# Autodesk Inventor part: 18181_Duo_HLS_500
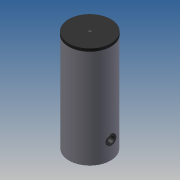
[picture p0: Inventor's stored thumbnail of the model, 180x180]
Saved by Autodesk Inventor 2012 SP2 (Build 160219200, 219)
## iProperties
allow_slope_adjustment: 0 ul
connection_type: 13 ul
flow_configuration2: 1 ul
flow_direction: 2 ul
loss_method: 0 ul
radius: 12,250 mm
radius: 19,625 mm
radius: 15,375 mm
description: 0:0:18181_Duo_HLS_500
manufacturer: 0:0:Flamco Group
model: 0:0:Duo HLS 500
url: 0:0:www.flamcogroup.com
Created: 2014-05
Part Number: 18181_Duo_HLS_500
Material: Default
Document SubType Name: Modeling
Designer: michel
Density: 1 g/cm^3
Author: michel
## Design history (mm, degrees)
sketch "Sketch1"
  geometry: C1 r 375 at (0, 0); 1 further point
  constraints: 1 centre point, 1 coincident
  dimensions: "d0" = 750 diameter of C1
extrude "Extrusion1" new body sketch "Sketch1" distance "d1" = 1830; taper "d2" = 0 deg
sketch "Sketch2"
  geometry: L1 (-375, 1830)-(375, 1830) reference; L2 (-375, 0)-(375, 0) reference; L3 (-375, 0)-(-375, 1830) reference; L4 (0, -326)-(0, 1956) reference; L5 (-504, 70)-(536, 70); L6 (-504, 330)-(536, 330); L7 (-490, 990)-(536, 990); L8 (-490, 1090)-(536, 1090); L9 (-490, 1670)-(536, 1670); L10 (375, 70)-(335, 70); L11 (335, 70)-(335, 86.625); L12 (335, 86.625)-(375, 86.625); L13 (375, 86.625)-(375, 70); L14 (335, 53.375)-(376, 53.375); L15 (376, 53.375)-(376, 54.625); L16 (376, 54.625)-(335, 54.625); L17 (335, 54.625)-(335, 53.375); L18 (375, 330)-(335, 330); L19 (335, 330)-(335, 350.955); L20 (335, 350.955)-(375, 350.955); L21 (375, 350.955)-(375, 330); L22 (335, 309.045)-(376, 309.045); L23 (376, 309.045)-(376, 310.375); L24 (376, 310.375)-(335, 310.375); L25 (335, 310.375)-(335, 309.045); L26 (375, 990)-(335, 990); L27 (335, 990)-(335, 1003.22); L28 (335, 1003.22)-(375, 1003.22); L29 (375, 1003.22)-(375, 990); L30 (335, 977.75)-(376, 977.75); L31 (376, 977.75)-(376, 976.78); L32 (376, 976.78)-(335, 976.78); L33 (335, 976.78)-(335, 977.75); L34 (375, 1090)-(335, 1090); L35 (335, 1090)-(335, 1110.955); L36 (335, 1110.955)-(375, 1110.955); L37 (375, 1110.955)-(375, 1090); L38 (335, 1069.045)-(376, 1069.045); L39 (376, 1069.045)-(376, 1070.375); L40 (376, 1070.375)-(335, 1070.375); L41 (335, 1070.375)-(335, 1069.045); L42 (375, 1670)-(335, 1670); L43 (335, 1670)-(335, 1686.625); L44 (335, 1686.625)-(375, 1686.625); L45 (375, 1686.625)-(375, 1670); L46 (335, 1653.375)-(376, 1653.375); L47 (376, 1653.375)-(376, 1654.625); L48 (376, 1654.625)-(335, 1654.625); L49 (335, 1654.625)-(335, 1653.375); L50 (0, 330)-(-504, 330); L51 (-375, 330)-(-387.5, 330); L52 (-387.5, 330)-(-387.5, 420); L53 (-387.5, 420)-(-375, 420); L54 (-375, 420)-(-375, 330); L55 (375, 1830)-(380, 1830); L56 (380, 1830)-(380, 1780); L57 (380, 1780)-(375, 1780); L58 (375, 1780)-(375, 1830); 2 further points
  constraints: 108 end point, 28 parallel, 13 perpendicular, 12 horizontal, 8 point on line, 6 other
  dimensions: "d6" = 70 distance from line of point (0, 0) L5; "d7" = 330 distance from line of point (0, 0) L6; "d8" = 990 distance from line of point (0, 0) L7; "d9" = 1090 distance between parallel lines of L2 L8; "d10" = 1670 distance from line of point (0, 0) L9; "d15" = 16.625 distance of L10.end L11.end; "d16" = 16.625 distance between parallel lines of L5 L12 (derived); "d17" = 16.625 distance between parallel lines of L14 L5 (= d15); "d18" = 1.25 distance between parallel lines of L16 L14 (computed from d16); "d19" = 1 dimension on L15; "d22" = 40 distance from line of L12.end L11; "d23" = 41 distance from line of L14.end L17; "d24" = 20.955 distance of L18.end L19.end; "d25" = 40 distance from line of L20.end L19; "d26" = 20.955 distance between parallel lines of L6 L20 (derived); "d27" = 20.955 distance between parallel lines of L6 L22 (= d24); "d28" = 1.33 distance between parallel lines of L24 L22 (computed from d24); "d29" = 1 dimension on L23; "d30" = 41 distance between parallel lines of L23 L25; "d33" = 13.22 distance of L26.end L27.end; "d34" = 13.22 distance between parallel lines of L7 L28 (derived); "d35" = 40 dimension on L27; "d37" = 0.97 distance between parallel lines of L32 L30 (computed from d34); "d38" = 1 dimension on L31; "d39" = 41 distance between parallel lines of L31 L33; "d42" = 20.955 distance of L34.end L35.end; "d43" = 20.955 distance between parallel lines of L8 L36 (derived); "d44" = 40 distance from line of L36.end L35; "d45" = 20.955 distance between parallel lines of L38 L8 (= d42); "d46" = 1.33 distance between parallel lines of L40 L38 (computed from d42); "d47" = 1 dimension on L39; "d48" = 41 distance between parallel lines of L39 L41; "d49" = 16.625 distance of L42.end L43.end; "d50" = 40 distance from line of L44.end L43; "d51" = 16.625 distance between parallel lines of L9 L44 (derived); "d52" = 16.625 distance between parallel lines of L46 L9 (= d49); "d53" = 1.25 distance between parallel lines of L48 L46 (computed from d49); "d54" = 1 dimension on L47; "d55" = 41 distance between parallel lines of L47 L49; "d80" = 330 distance from line of point (0, 0) L50; "d81" = 12.5 distance of L52.end L53.end; "d82" = 90 distance of L51.end L52.end; "d83" = 90 distance between parallel lines of L50 L53 (derived); "d109" = 13.22 distance between parallel lines of L7 L32 (= d33); "d110" = 5 distance of L56.end L57.end; "d111" = 50 distance of L55.end L56.end
  node "Projected Loop1"
revolve "Revolution1" stored, may be unused: angle "d5" = 90 deg
revolve "Revolution2" stored, may be unused: angle "d20" = 90 deg
revolve "Revolution3" stored, may be unused: angle "d21" = 90 deg
revolve "Revolution4" stored, may be unused: angle "d31" = 90 deg
revolve "Revolution5" stored, may be unused: angle "d32" = 90 deg
revolve "Revolution6" stored, may be unused: angle "d40" = 90 deg
revolve "Revolution7" stored, may be unused: angle "d41" = 90 deg
revolve "Revolution8" stored, may be unused: angle "d72" = 90 deg
revolve "Revolution9" stored, may be unused: angle "d73" = 90 deg
revolve "Revolution10" stored, may be unused: angle "d74" = 90 deg
revolve "Revolution11" stored, may be unused: angle "d75" = 90 deg
revolve "Revolution16" stored, may be unused: angle "d84" = 90 deg
sketch "Sketch3"
  geometry: C1 r 62.5 at (0, 0); A1 r 90 centre (0, 0) between (90, 0) and (-90, 0) reference; 1 further point
  constraints: 1 centre point, 1 coincident
  dimensions: "d85" = 125 diameter of C1
extrude "Extrusion2" join sketch "Sketch3" stored distance "d86" = 1450; taper "d87" = 0 deg
sketch "Sketch4"
  geometry: C1 r 90 at (0, 0) reference; C2 r 55 at (0, 0); 1 further point
  constraints: 1 centre point, 1 coincident
  dimensions: "d88" = 110 diameter of C2
extrude "Extrusion3" cut sketch "Sketch4" distance "d89" = 80; taper "d90" = 0 deg
workplane "Work Plane1"
sketch "Sketch6"
  geometry: C1 r 335 at (0, 0) reference; C2 r 20.955 at (0, 0); C3 r 19.625 at (0, 0)
  constraints: 2 centre point, 2 coincident
  dimensions: "d103" = 41.91 diameter of C2; "d104" = 39.25 diameter of C3
extrude "Extrusion4" cut sketch "Sketch6" distance "d105" = 40; taper "d106" = 0 deg
extrude "Extrusion5" join sketch "Sketch6" distance "d107" = 2; taper "d108" = 0 deg
body "Solid1"
other parameters: "d91" = 45 deg
